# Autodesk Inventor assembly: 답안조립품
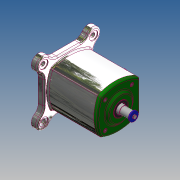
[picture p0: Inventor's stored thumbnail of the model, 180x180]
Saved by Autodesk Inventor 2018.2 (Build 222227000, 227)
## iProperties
Created: 2022-01
Part Number: 답안조립품
Document SubType Name: Assembly
Designer: woori
Author: woori
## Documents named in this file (13)
- C:\Users\woori\Desktop\720106V1015\답안조립품.iam
- C:\Users\woori\Desktop\720106V1015\본체.ipt
- C:\Users\woori\Desktop\720106V1015\편심축.ipt
- C:\Users\woori\Desktop\720106V1015\커버.ipt
- C:\Users\woori\Desktop\720106V1015\베어링 6203.ipt
- C:\Users\woori\Desktop\720106V1015\오일 실 17 x 30 x 8.ipt
- C:\Users\woori\Desktop\720106V1015\키 5 x 5.ipt
- C:\Users\woori\Desktop\720106V1015\스프로킷.ipt
- C:\Users\woori\Desktop\720106V1015\부시.ipt
- C:\Users\woori\Desktop\720106V1015\슬라이더.ipt
- C:\Users\woori\Desktop\720106V1015\와셔 4 x 20.ipt
- C:\Users\woori\Desktop\720106V1015\볼트 M4 x 12.ipt
- C:\Users\woori\Desktop\720106V1015\육각머리볼트 M4.ipt
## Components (8 placed, 1 different names)
1. M4x0.7x12:1
2. M4x0.7x12:2
3. M4x0.7x12:3
4. M4x0.7x12:4
5. M4x0.7x12:5
6. M4x0.7x12:6
7. M4x0.7x12:7
8. M4x0.7x12:8
